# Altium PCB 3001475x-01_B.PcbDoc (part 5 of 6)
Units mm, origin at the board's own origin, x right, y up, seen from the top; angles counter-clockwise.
Board outline 335 x 91 mm, 12 copper layers (Top Layer, L2 GND, Layer 3, L4 GND, Layer 5, L6 PWR, L7 3V3, Layer 8, L9 GND, Layer 10, L11 GND, Bottom Layer), stack 1.59 mm thick; 339 components, 431 nets, 1732 pads, 1526 vias.
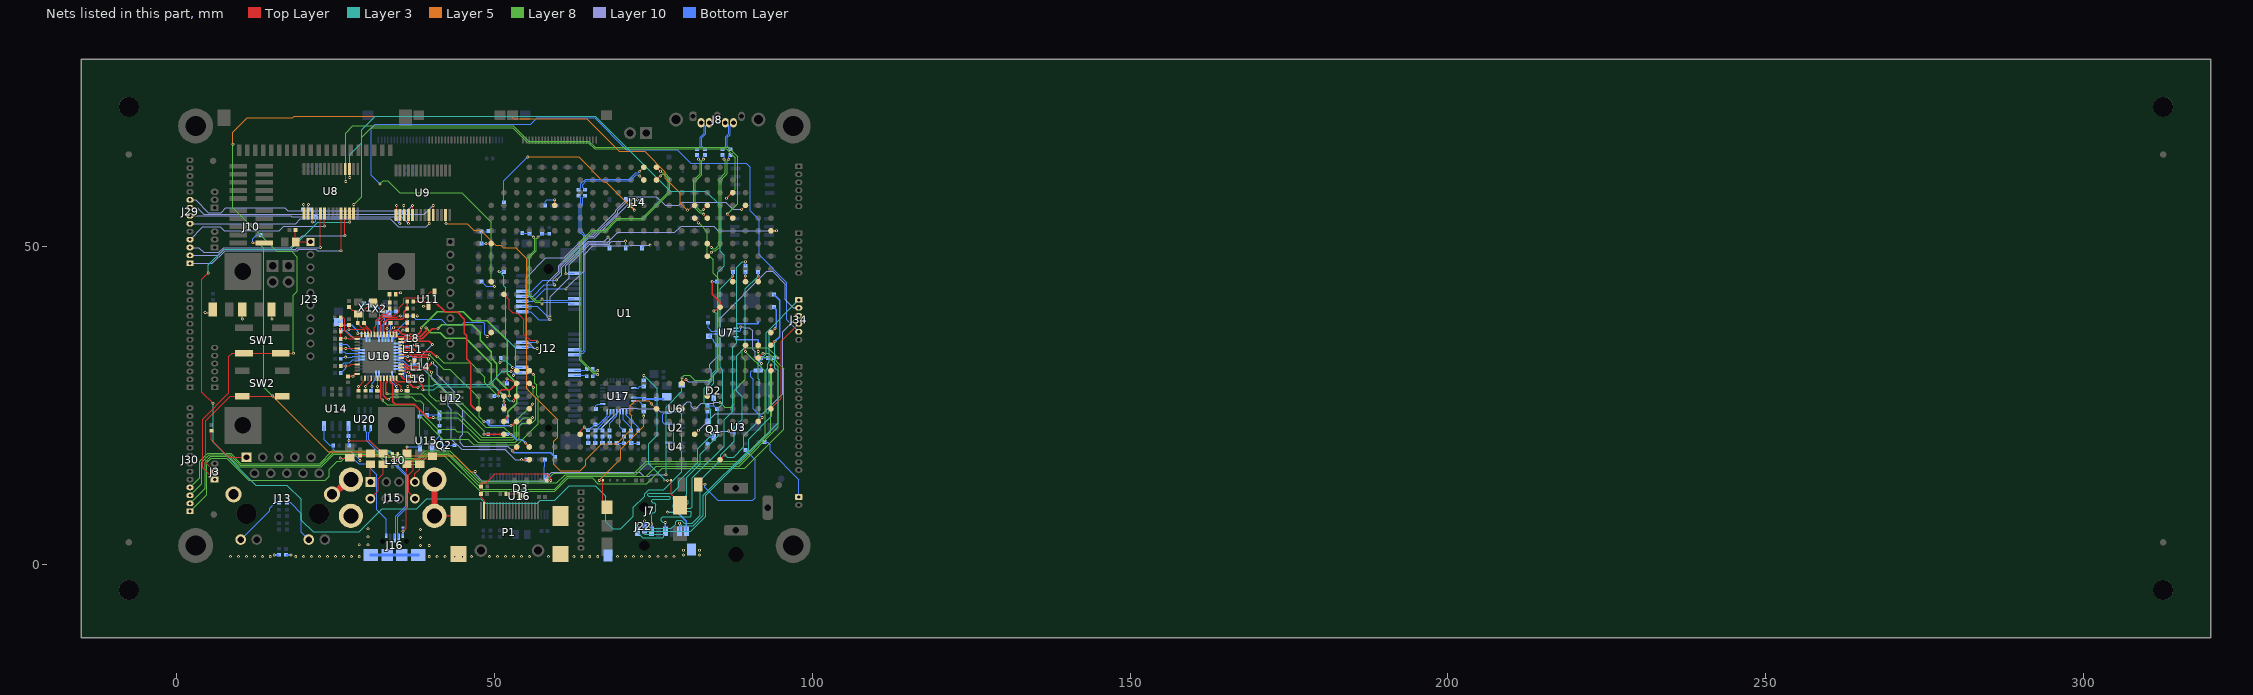
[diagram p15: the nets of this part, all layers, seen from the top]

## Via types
v1: diameter 0.45, hole 0.2, Top Layer to Bottom Layer, 1511 vias
v2: diameter 0.5, hole 0.2, Top Layer to Bottom Layer, 14 vias
v3: diameter 0.45/0.45/0.45/0.45/0.45/0.45/0.45/0.45/0.45/0.45/0.45/0.45 (per signal layer), hole 0.2, Top Layer to Bottom Layer, 1 vias

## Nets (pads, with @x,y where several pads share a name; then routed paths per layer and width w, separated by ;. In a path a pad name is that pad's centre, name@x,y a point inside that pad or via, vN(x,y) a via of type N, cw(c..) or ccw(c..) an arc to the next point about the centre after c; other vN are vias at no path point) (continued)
NetC22_1: C22.1 U8.1 | length 2
  Top Layer w0.125: U8.1@20,55.297 v1(20,56.625)
  Bottom Layer w0.125: C22.1@20,55.96 v1(20,56.625)
NetC22_2: C22.2 U8.2 | length 2
  Top Layer w0.125: U8.2@20.75,55.303 v1(20.75,56.625)
  Bottom Layer w0.125: C22.2@20.75,55.96 v1(20.75,56.625)
NetC23_1: C23.1 U9.1 | length 2.4
  Top Layer w0.125: U9.1@34.625,55.1 v1(34.625,56.5)
  Bottom Layer w0.125: C23.1@34.625,55.46 v1(34.625,56.5)
NetC23_2: C23.2 U9.2 | length 2.4
  Top Layer w0.125: v1(35.125,53.625) U9.2@35.125,54.95
  Bottom Layer w0.125: C23.2@34.625,54.54 34.625,54.125 v1(35.125,53.625)
NetC24_1: C24.1 U8.3 | length 2.6
  Top Layer w0.125: v1(21.375,53.875) U8.3@21.375,55.222
  Bottom Layer w0.125: v1(21.375,53.875) 21.75,53.875 21.875,54 C24.1@21.875,54.665
NetC25_1: C25.1 U9.3 | length 2.5
  Top Layer w0.125: U9.3@35.75,55.075 v1(35.75,56.5)
  Bottom Layer w0.125: C25.1@35.75,55.46 v1(35.75,56.5)
NetC28_2: C28.2 R39.2 U10.46 X1.1 | length 6.1
  Top Layer w0.125: C28.2@27.125,40.54 27.665,40 28.025,40 X1.1@28.6,39.425 ; R39.2@28.52,37.875 29.143,37.253 29.747,37.253 30.125,36.875 U10.46@30.125,36.2 ; R39.2@28.52,38 X1.1@28.52,39.425
NetC29_2: C29.2 J13.1 | length 8
  Top Layer w0.125: C29.2@5.5,21.04 5.5,19.625 8.235,16.89 J13.1@11,16.89
NetC30_2: C30.2 R39.1 U10.45 X1.3 | length 7.9
  Top Layer w0.125: X1.3@30.513,41.013 29.438,39.938 29.438,38.042 R39.1@29.48,38 29.48,37.874 30.625,36.729 U10.45@30.625,36.2 ; X1.3@30.9,41.325 31.09,41.325 C30.2@32.5,39.915
NetC42_2: C42.2 C43.2 C44.2 C45.2 L2.2 U10.1 U10.12 U10.47 | length 10.3
  Top Layer w0.125: C45.2@25.835,35.5 C42.2@25.835,36.625 L2.2@25.835,37.855 ; C45.2@25.96,35.625 v1(26.625,35.625) 27,35.625 27.125,35.5 U10.1@28.425,35.5 ; C44.2@27.125,37.665 v1(27.125,37.002) 29.498,37.002 29.625,36.875 U10.47@29.625,36.2
  Top Layer w0.25: C43.2@27.04,29.625 v1(27.75,29.625) 28.125,30 U10.12@28.425,30
NetC46_2: C46.2 C47.2 C48.2 C49.2 L3.1 U10.16 U10.34 U10.40 | length 8.2
  Top Layer w0.125: C46.2@29.75,27.335 v1(29.75,28) 29.75,28.125 30.625,29 U10.16@30.625,29.3 ; U10.40@33.125,36.2 v1(33.125,37.125) 33.125,37.46 C47.2@33.665,38 ; U10.34@35.325,34.5 v1(37.125,34.5) C48.2@37.79,34.5 ; L3.1@36.25,27.355 36.375,27.48 v1(36.375,28)
  Bottom Layer w0.125: C49.2@36.375,27.335 v1(36.375,28)
NetC50_2: C50.2 C51.2 C52.2 C53.2 C54.2 C55.2 C56.2 L4.1 U10.14 U10.18 U10.23 U10.26 U10.30 U10.39 | length 17.5
  Top Layer w0.125: C50.2@28.625,27.335 v1(28.625,28) 29.625,29 U10.14@29.625,29.3 ; C51.2@31.625,27.46 v1(31.625,28) U10.18@31.625,29.3 ; U10.39@33.625,36.2 33.625,36.75 v1(34.125,37.25) 34.25,37.375 36.29,37.375 ; U10.23@34.125,29.3 34.125,29 34.725,28.4 34.975,28.4 35.375,28 v1(35.375,27.375) 35.375,27.335 C52.2@34.625,27.335 ; U10.26@35.325,30.5 35.875,30.5 36.125,30.25 v1(36.5,30.25) C53.2@37.04,29.71 ; U10.30@35.325,32.5 35.875,32.5 36.375,32 v1(36.75,32) C54.2@37.165,32 ; C56.2@36.29,36.875 36.29,37.375 ; L4.1@36.29,39.25 C55.2@36.29,38 36.29,37.375
NetC60_2: C60.2 C61.2 L5.2 U10.44 | length 7.7
  Top Layer w0.125: U10.44@31.125,36.2 31.125,37.25 31.375,37.5 31.375,38.375 32.375,39.375 33.125,39.375 33.52,39.77 L5.2@33.52,42.5
NetC63_1: C63.1 R67.1 U13.32 X2.3 | length 7.6
  Bottom Layer w0.125: C63.1@29.535,41.05 X2.3@30.9,41.05 31.075,41.05 32,40.125 32,38.75 31.75,38.5 31.75,37.5 31.875,37.375 U13.32@31.875,35.55
NetC64_1: C64.1 R67.2 U13.33 X2.1 | length 5.7
  Bottom Layer w0.125: U13.33@32.375,35.55 32.375,37.645 R67.2@32.73,38 32.73,39.08 X2.1@33.1,39.45 33.44,39.79 C64.1@34.5,39.79
NetC66_2: C66.2 C67.2 L9.2 R72.1 U12.8 U15.S | length 13
  Top Layer w0.125: L9.2@36.25,17.475 v1(36.25,18.5)
  Bottom Layer w0.125: v1(36.25,18.5) U15.S@38.15,18.5 ; U15.S@38.3,18.55 38.663,18.913 38.663,19.712 38.25,20.125 C67.2@38.25,23.29 38.25,23.54 C66.2@39.375,23.54 ; C66.2@39.385,23.55 U12.8@41.345,23.55 ; R72.1@41.375,21.855 U12.8@41.375,23.52
NetC68_2: C68.2 C71.2 L7.2 U14.8 | length 11.6
  Top Layer w0.125: v1(28.875,16.375) C71.2@28.875,17.165 L7.2@30.19,17.165
  Bottom Layer w0.125: U14.8@23.22,21.8 23.22,19.655 24.125,18.75 C68.2@24.665,18.75 24.665,18.125 24.955,17.835 27.415,17.835 v1(28.875,16.375)
NetC69_2: C69.2 C70.2 L6.2 U14.5 | length 9.1
  Top Layer w0.125: v1(27.125,19.5) 30.375,19.5 32.4,17.475 L6.2@32.5,17.475
  Bottom Layer w0.125: C70.2@27.03,20.26 U14.5@27.03,21.8 ; C69.2@27.125,18.79 v1(27.125,19.5) C70.2@27.125,20.165
NetC72_2: C72.2 C73.2 C74.2 C75.2 C76.2 C77.2 L17.1 U13.5 U13.10 U13.15 U13.23 U13.29 U13.36 | length 21.4
  Bottom Layer w0.125: C77.2@25.835,32.625 v1(26.625,32.625) 27.625,32.625 27.75,32.75 U13.23@29.075,32.75 ; v1(28.5,36.375) 30.25,36.375 30.375,36.25 U13.29@30.375,35.55 ; C73.2@30.75,27.335 v1(30.75,28) 30.75,28.5 31.375,29.125 U13.15@31.375,29.95 ; U13.10@33.875,29.95 33.875,28.75 v1(34.625,28) C74.2@34.625,27.335 ; U13.36@33.875,35.55 34.175,35.55 35.5,36.875 v1(35.625,36.875) C76.2@36.29,36.875 ; U13.5@34.675,32.75 v1(36.375,32.75) 37.125,32.75 37.29,32.585 C75.2@37.29,32.5
  Bottom Layer w0.25: L17.1@25.5,38.15 25.985,37.665 C72.2@27.125,37.665 27.585,37.665 28.5,36.75 v1(28.5,36.375)
NetC78_2: C78.2 U13.14 | length 2.9
  Bottom Layer w0.125: C78.2@31.75,27.335 32.125,27.71 32.125,28.75 31.875,29 U13.14@31.875,29.95
NetC79_2: C79.2 U13.34 | length 2.8
  Bottom Layer w0.125: U13.34@32.875,35.55 32.875,36.25 33.665,37.04 C79.2@33.665,38
NetC84_2: C84.2 U16.37 | length 2.9
  Bottom Layer w0.138: U16.37@57.875,13.65 57.875,15.375 57.96,15.46 C84.2@57.96,16.5
NetC86_2: C86.2 P1.18 R85.2 R87.2 U16.38 | length 18.2
  Top Layer w0.125: R85.2@47.895,12.25 47.895,12.77 48,12.875 48.75,12.875 50.125,14.25 58.25,14.25 58.875,13.625 v1(58.875,13.25) R87.2@58.23,13.25 ; R85.2@47.915,12.25 C86.2@47.915,11.125 47.915,10.585 48.375,10.125 P1.18@48.375,8.5
  Bottom Layer w0.125: U16.38@58.375,13.65 58.375,13.25 v1(58.875,13.25)
NetC87_1: C87.1 U17.11 | length 3.5
  Bottom Layer w0.125: U17.11@70.25,24.05 70.25,22.75 71.5,21.5 C87.1@71.5,21.085
NetC87_2: C87.2 L18.1 R92.2 | length 2.2
  Bottom Layer w0.125: C87.2@71.5,20.165 L18.1@71.5,19.105 R92.2@72.625,19.105
NetC88_1: C88.1 U17.12 | length 3.2
  Bottom Layer w0.125: U17.12@69.75,24.05 69.75,21.71 C88.1@70.375,21.085
NetC88_2: C88.2 L19.1 R91.2 | length 2.2
  Bottom Layer w0.125: L19.1@69.25,19.105 R91.2@70.375,19.105 C88.2@70.375,20.165
NetC89_2: C89.2 U17.18 | length 1.7
  Bottom Layer w0.125: C89.2@65.96,24.5 65.96,24.96 66.25,25.25 U17.18@67.05,25.25
NetC90_2: C90.2 U17.10 | length 3.7
  Bottom Layer w0.125: U17.10@70.75,24.05 70.75,23.5 72.625,21.625 C90.2@72.625,21.085
NetC91_1: C91.1 L20.2 | length 1.1
  Bottom Layer w0.125: L20.2@68.125,19.105 C91.1@68.125,20.165
NetC91_2: C91.2 U17.13 | length 3.4
  Bottom Layer w0.125: C91.2@68.125,21.085 68.125,22.25 69.25,23.375 U17.13@69.25,24.05
NetC92_1: C92.1 L21.2 | length 1.1
  Bottom Layer w0.125: L21.2@67,19.105 C92.1@67,20.165
NetC92_2: C92.2 U17.14 | length 3.7
  Bottom Layer w0.125: C92.2@67,21.085 67,21.625 68.75,23.375 U17.14@68.75,24.05
NetC93_1: C93.1 L22.2 | length 1.1
  Bottom Layer w0.125: L22.2@65.875,19.105 C93.1@65.875,20.165
NetC93_2: C93.2 U17.15 | length 3.9
  Bottom Layer w0.125: C93.2@65.875,21.085 68.25,23.46 U17.15@68.25,24.05
NetC94_2: C94.2 R94.2 U17.16 | length 4.6
  Bottom Layer w0.125: R94.2@64.75,21.105 65.25,21.605 65.355,21.605 65.79,22.04 C94.2@65.875,22.04 66.415,22.04 67.75,23.375 U17.16@67.75,24.05
NetC97_2: C97.2 C98.2 L26.2 U17.5 | length 4.8
  Bottom Layer w0.25: U17.5@71.95,26.25 73.25,26.25 73.46,26.04 C98.2@75.5,26.04 L26.2@76.64,26.04
NetC101_2: C101.2 J23.1 L28.1 | length 4.2
  Top Layer w0.15: L28.1@18.71,50.765 C101.2@18.71,52.625 ; L28.1@18.725,50.75 J23.1@21.064,50.75
NetD1_A: D1.A R12.1 | length 18.6
  Top Layer w0.125: D1.A@82.05,12.625 v1(83.125,12.625)
  Bottom Layer w0.125: v1(83.125,12.625) 83.125,12.125 85.125,10.125 90.625,10.125 91,10.5 91,16.52 R12.1@89.5,18.02
NetD2_K: D2.K R11.1 R13.1 | length 2.9
  Bottom Layer w0.125: R13.1@83.52,25 84.5,25 ; D2.K@84.5,26.225 84.5,25 ; R11.1@85.02,24.5 84.52,25 84.5,25
NetD3_K: D3.K R86.1 | length 2.2
  Top Layer w0.125: R86.1@51.855,11.125 D3.K@54.1,11.125
NetD4_A: D4.A R119.1 | length 2.5
  Top Layer w0.125: v1(15,38.625) D4.A@15,40.075
  Bottom Layer w0.125: v1(15,38.625) R119.1@15,39.645
NetD5_A: D5.A R120.1 | length 2.5
  Top Layer w0.125: v1(10.375,38.625) D5.A@10.375,40.075
  Bottom Layer w0.125: v1(10.375,38.625) R120.1@10.375,39.645
NetD6_A: D6.A R121.1 | length 2
  Top Layer w0.125: v1(4.5,39.645) D6.A@5.22,39.645
  Bottom Layer w0.125: v1(4.5,39.645) R121.1@5.75,39.645
NetD7_2: D7.2 J22.3 L25.2 | length 17.9
  Top Layer w0.125: v1(66.5,13.25) D7.2@67.075,13.25 J22.3@67.075,9.625
  Layer 5 w0.125: v1(66.5,13.25) 69.875,16.625 69.875,18.125 73.5,21.75 v1(73.5,23.35) v1@73.5,23.375
  Bottom Layer w0.125: v1(73.5,23.35) L25.2@73.5,24.02
NetD8_2: D8.2 J22.2 L24.2 | length 24.9
  Top Layer w0.125: v1(77.25,13.25) D8.2@77.8,13.25 77.8,11.075 J22.2@79.2,9.675
  Layer 3 w0.125: v1(73.5,29.75) 75.625,27.625 75.625,20.375 74.25,19 74.25,15.875 76.875,13.25 v1(77.25,13.25)
  Bottom Layer w0.125: L24.2@73.5,28.98 v1(73.5,29.75)
NetD10_2: D10.2 J16.1 L9.1 | length 12.1
  Top Layer w0.125: v1(35.625,5.25) 36.125,5.75 36.125,14.625 36.25,14.75 L9.1@36.25,15.775
  Bottom Layer w0.125: J16.1@35.625,4.525 v1(35.625,5.25) D10.2@35.625,5.825
NetJ2_1: J2.1 R8.1 | length 11.2
  Bottom Layer w0.125: R8.1@92.48,19.25 93,19.25 93.375,18.875 93.375,17.875 97.875,13.375 J2.1@97.875,10.625
NetJ7_5: J7.5 R35.2 | length 54
  Layer 3 w0.104: v1(76.875,6.625) 76.5,6.625 76.25,6.875 76.25,7.25 76.5,7.5 80.833,7.5 81,7.667 81,8.25 80.875,8.375 79.875,8.375 79.75,8.5 79.75,8.75 79.875,8.875 80.875,8.875 81.125,9.125 81.125,13.625 86.125,18.625 86.125,22.75 87.5,24.125 87.5,34.25 88.125,34.875 88.125,46.75 89,47.625 v1(89.5,47.625)
  Bottom Layer w0.2: J7.5@76.875,5.275 v1(76.875,6.625) ; R35.2@89.5,46.98 v1(89.5,47.625)
NetJ13_D1: J13.D1 R45.1 | length 8.7
  Bottom Layer w0.125: J13.D1@10.086,3.936 14.625,8.475 14.625,8.875 15.52,9.77 R45.1@16.125,9.77
NetJ13_D3: J13.D3 R38.1 | length 7.5
  Bottom Layer w0.125: R38.1@17.375,9.77 17.855,9.77 19.625,8 19.625,5.115 J13.D3@20.804,3.936
NetJ15_A1: J15.A1 L7.1 | length 2.8
  Top Layer w0.125: J15.A1@30.5,13 L7.1@30.5,15.775
NetJ15_A4: J15.A4 L13.2 | length 3.1
  Top Layer w0.125: J15.A4@37.5,13 37.5,14.25 38.25,15 L13.2@38.25,15.775
NetJ15_B1: J15.B1 L6.1 | length 6.2
  Top Layer w0.125: J15.B1@30.5,10.38 31.75,11.63 31.75,13.5 32.5,14.25 L6.1@32.5,15.775
NetJ15_B4: J15.B4 L12.2 | length 10.1
  Top Layer w0.125: J15.B4@37.5,10.38 36.5,11.38 36.5,14.125 37.25,14.875 37.25,16.5 37.375,16.625 39.85,16.625 L12.2@40.25,17.025
NetJ16_5: J16.5 L15.2 | length 18.6
  Top Layer w0.125: v1(25.75,16.75) L15.2@27.225,16.75
  Bottom Layer w0.125: v1(25.75,16.75) 27.75,16.75 28.625,15.875 29.75,15.875 31.5,14.125 31.5,8.625 33,7.125 J16.5@33,4.525 J16.5@33,4.5
NetL1_1: L1.1 U7.5 | length 4.5
  Bottom Layer w0.25: U7.5@88,37.175 88.125,37.3 88.125,37.875 91.5,37.875 L1.1@91.5,38.1 L1.1@91.5,38.225
NetL1_2: L1.2 U7.8 | length 4.4
  Bottom Layer w0.25: U7.8@88,35.825 88,35.375 91.5,35.375 L1.2@91.5,34.9
NetL8_1: L8.1 U13.1 | length 2.2
  Bottom Layer w0.125: U13.1@34.675,34.75 35,34.75 35.5,35.25 35.5,35.5 35.9,35.9 L8.1@36.275,35.9
NetL8_4: L8.4 U13.2 | length 2
  Bottom Layer w0.125: U13.2@34.675,34.25 35.125,34.25 35.975,35.1 L8.4@36.275,35.1
NetL11_1: L11.1 U13.3 | length 1.8
  Bottom Layer w0.125: U13.3@34.675,33.75 35.5,33.75 36.025,34.275 L11.1@36.275,34.275
NetL11_4: L11.4 U13.4 | length 1.7
  Bottom Layer w0.125: U13.4@34.675,33.25 35.75,33.25 36,33.5 L11.4@36.275,33.5
NetL14_1: L14.1 U13.6 | length 3.3
  Bottom Layer w0.125: U13.6@34.675,32.25 35.5,32.25 36.375,31.375 37.375,31.375 L14.1@37.525,31.525
NetL14_4: L14.4 U13.7 | length 3.1
  Bottom Layer w0.125: U13.7@34.675,31.75 35.5,31.75 36.525,30.725 L14.4@37.4,30.725
NetL16_1: L16.1 U13.8 | length 3.2
  Bottom Layer w0.125: U13.8@34.675,31.25 35.375,31.25 36,30.625 36,29.875 36.225,29.65 L16.1@36.775,29.65
NetL16_4: L16.4 U13.9 | length 3.3
  Bottom Layer w0.125: U13.9@34.675,30.75 35.375,30.75 35.625,30.5 35.625,29.75 36.525,28.85 L16.4@36.775,28.85
NetL23_2: L23.2 R94.1 | length 1
  Bottom Layer w0.125: L23.2@64.75,19.105 R94.1@64.75,20.145
NetL24_1: L24.1 U17.2 | length 1.7
  Bottom Layer w0.125: U17.2@71.95,27.75 72.625,27.75 72.895,28.02 L24.1@73.5,28.02
NetL25_1: L25.1 U17.6 | length 1.9
  Bottom Layer w0.125: U17.6@71.95,25.75 72.73,25.75 L25.1@73.5,24.98
NetQ1_1: Q1.1 R13.2 | length 1.5
  Bottom Layer w0.125: Q1.1@83.5,22.5 R13.2@83.5,24.02
NetQ1_3: Q1.3 R14.2 U3.3 | length 6.2
  Layer 10 w0.125: v1(84.5,21) v1(86.875,21)
  Bottom Layer w0.125: R14.2@83.5,18.98 83.5,19.75 83.8,20.05 Q1.3@84.5,20.05 v1(84.5,21) ; v1(86.875,21) 87.16,20.715 U3.3@87.725,20.715
NetQ2_D: Q2.D R72.2 U15.G | length 4.7
  Bottom Layer w0.125: U15.G@40.2,18.35 40.2,19.075 41.375,20.25 R72.2@41.375,20.895 ; U15.G@40.49,18.06 Q2.D@42.125,18.06
NetQ2_G: Q2.G R75.2 | length 2.7
  Bottom Layer w0.125: Q2.G@41.625,19.44 41.625,19 41.855,18.77 R75.2@43.75,18.77
NetR1_1: R1.1 R2.1 R3.1 U1.G2 | length 4.3
  Top Layer w0.125: v1(48.675,50.5) U1.G2@49.5,50.5
  Bottom Layer w0.125: v1(48.675,50.5) R1.1@47.98,50.5 R3.1@47.98,52.375 R2.1@48.895,52.375
NetR4_1: R4.1 U1.D13 | length 29.8
  Top Layer w0.125: U1.D13@71.5,56.5 v1(72,55.75)
  Layer 5 w0.125: v1(55.25,64.125) 63.25,64.125 67.125,60.25 67.5,60.25 v1(72,55.75)
  Bottom Layer w0.125: R4.1@51.5,56.98 51.5,60.375 v1(55.25,64.125)
NetR5_2: R5.2 U1.D7 | length 3.1
  Top Layer w0.125: U1.D7@59.5,56.5 v1(59.5,57.375)
  Bottom Layer w0.125: R5.2@57.98,56.5 57.98,57.105 58.25,57.375 v1(59.5,57.375)
NetR22_1: R22.1 R123.2 R124.2 U7.6 | length 12.2
  Layer 10 w0.125: v1(88.75,37.375) 89.125,37.375 89.25,37.25 90.125,37.25 90.625,36.75 90.625,33.875 91,33.5 91,32.625 v1(92,31.625)
  Bottom Layer w0.125: U7.6@88,36.725 88.6,36.725 88.75,36.875 v1(88.75,37.375) ; R123.2@91.98,30.5 R22.1@91.98,32.5 R124.2@93.02,32.5
NetR23_1: R23.1 R27.2 U7.2 | length 3.4
  Bottom Layer w0.125: U7.2@85,36.275 84.1,36.275 R27.2@83.75,35.925 83.825,35.925 84.5,35.25 84.5,35.02 R23.1@85.02,34.5
NetR26_2: R26.2 U7.3 | length 2.4
  Bottom Layer w0.125: R26.2@83.625,38.02 83.625,37.25 84.15,36.725 U7.3@85,36.725
NetR48_2: R48.2 R50.2 U10.41 | length 8
  Top Layer w0.2: U10.41@32.625,36.2 32.625,38 33.2,38.575 35.45,38.575 35.725,38.85 35.725,39.705 R50.2@36.27,40.25 R48.2@36.27,41.375
NetR49_2: R49.2 U10.48 | length 5.6
  Top Layer w0.125: R49.2@25.855,38.875 26.25,38.875 26.5,38.625 26.5,36.75 27.375,35.875 U10.48@29.125,35.875
NetR68_1: R68.1 U13.28 | length 4.6
  Bottom Layer w0.125: R68.1@25.855,36.875 26.625,36.875 27.95,35.55 U13.28@29.875,35.55
NetR70_2: R70.2 U13.35 | length 4.3
  Bottom Layer w0.125: U13.35@33.375,35.55 33.375,36.25 33.75,36.625 34.5,36.625 35.875,38 R70.2@36.27,38
NetR71_2: R71.2 U13.22 | length 3.6
  Bottom Layer w0.125: R71.2@25.875,31.25 26.375,31.75 27.25,31.75 27.75,32.25 U13.22@29.075,32.25
NetR73_2: R73.2 U13.24 | length 3.3
  Bottom Layer w0.125: R73.2@25.855,33.5 26.375,33.5 26.625,33.25 U13.24@29.075,33.25
NetR74_2: R74.2 U13.25 | length 3.6
  Bottom Layer w0.125: R74.2@25.855,34.625 26.75,34.625 27.625,33.75 U13.25@29.075,33.75
NetU2_6: U2.6 U4.6 U6.4 | length 7.6
  Bottom Layer w0.125: U6.4@77.375,23.875 76.75,23.875 76.5,23.625 76.5,22.4 76.75,22.15 U2.6@77.4,22.15 78,22.15 78.25,21.9 78.25,19.375 78.025,19.15 U4.6@77.4,19.15
NetU10_43: U10.43 U11.G | length 13.7
  Top Layer w0.125: U10.43@31.625,36.2 31.625,38.25 32.5,39.125 34.25,39.125 35,39.875 35,40.375 35.75,41.125 35.75,41.875 35.875,42 39.125,42 40.025,42.9 U11.G@40.575,42.9
ON/OFF: J3.1 SW1.3 SW1.4 U1.D18 | length 154.2
  Top Layer w0.125: J3.1@6,13.375 4.125,15.25 4.125,22.875 8.25,27 8.25,32.75 8.75,33.25 SW1.3@10.6,33.25 SW1.4@16.4,33.25 v1(18.375,33.25) ; v1(80.375,55.75) U1.D18@81.5,56.5
  Layer 8 w0.125: v1(8.875,66.125) 8.875,56.125 15.75,49.25 18.125,49.25 19,48.375 19,43 18.375,42.375 v1(18.375,33.25)
  Layer 5 w0.125: v1(8.875,66.125) 8.875,68 11.125,70.25 18.25,70.25 18.5,70.5 52.625,70.5 53,70.125 64.5,70.125 69.625,65 73.625,65 76.875,61.75 76.875,60.75 79.25,58.375 79.25,56.875 v1(80.375,55.75)
OTGD_N: J16.2 L10.2 U20.4 | length 22.8
  Top Layer w0.155: v1(34.75,16.375) 34.75,16.673 34.775,16.698 L10.2@34.775,17.225
  Bottom Layer w0.155: U20.4@30.575,21.475 30.575,21.075 30.242,20.742 30.242,19.607 31.965,17.885 33.643,17.885 34.518,17.011 34.518,16.607 v1(34.75,16.375) 34.518,16.143 34.518,15.886 36.4,14.003 36.4,9.133 34.767,7.5 34.767,4.932 34.95,4.75 J16.2@34.95,4.15
OTGD_P: J16.3 L10.3 U20.5 | length 22.8
  Top Layer w0.155: L10.3@33.975,17.225 33.975,16.698 34,16.673 v1(34,16.375)
  Bottom Layer w0.155: U20.5@29.625,21.475 29.625,21.1 29.957,20.768 29.957,19.489 31.847,17.6 33.525,17.6 34.232,16.893 34.232,16.607 v1(34,16.375) 34.232,16.143 34.232,15.767 36.115,13.885 36.115,9.251 34.482,7.618 34.482,4.932 34.3,4.75 J16.3@34.3,4.15
PCIE_DIS_N: J12.20 U1.L3 | length 13
  Top Layer w0.125: U1.L3@51.5,42.5 52.375,41.625 52.375,40.125 52.875,39.625 53.625,39.625 54.625,38.625 54.625,36.25 55.625,35.25 56.5,35.25 v1(56.75,35)
  Bottom Layer w0.125: J12.20@54.4,35 v1(56.75,35)
PCIE_I2C_SCL: J12.30 R95.2 | length 4.8
  Layer 3 w0.125: v1(50.875,31.8) 51.125,32.05 51.825,32.05 v1(52.875,31)
  Bottom Layer w0.125: v1(50.875,31.8) 50.875,32.355 R95.2@51.02,32.5 ; v1(52.875,31) J12.30@54.4,31
PCIE_I2C_SDA: J12.32 R96.2 | length 20.2
  Layer 3 w0.125: v1(50.75,46.125) 51.5,45.375 51.5,43.828 51.75,43.578 51.75,35.625 53.375,34 53.375,30.125 v1(53,29.75)
  Bottom Layer w0.125: v1(50.75,46.125) 51.395,46.125 R96.2@51.5,46.02 ; v1(53,29.75) 53,30.125 53.075,30.2 J12.32@54.4,30.2
PCIE_RESET_N: J12.22 U1.D22 | length 56
  Top Layer w0.125: v1(88.875,55.875) U1.D22@89.5,56.5
  Layer 10 w0.125: v1(56.75,34) 56.25,34 55,35.25 55,45.146 58.104,48.25 61,48.25 64.625,51.875 65.5,51.875 69.125,55.5 69.125,55.75 71.25,57.875 75.5,57.875 76.875,56.5 79,56.5 79.5,57 86.375,57 87.5,55.875 v1(88.875,55.875)
  Bottom Layer w0.125: J12.22@54.4,34.2 55.925,34.2 56.125,34 v1(56.75,34)
PCIE_RX_N: R44.1 U1.A14 | length 12
  Top Layer w0.175: v1(72.875,61.875) U1.A14@73.5,62.5
  Bottom Layer w0.175: R44.1@63.25,58.98 63.6,59.33 63.6,59.9 64.35,60.65 71.225,60.65 72.225,61.65 72.65,61.65 v1(72.875,61.875)
PCIE_RX_P: R47.1 U1.B14 | length 11.5
  Top Layer w0.175: v1(72.875,61.125) U1.B14@73.5,60.5
  Bottom Layer w0.175: R47.1@64.25,58.98 63.9,59.33 63.9,59.776 64.474,60.35 71.349,60.35 72.349,61.35 72.65,61.35 v1(72.875,61.125)
PCIE_TX_N: R51.1 U1.A15 | length 45
  Top Layer w0.175: U1.A15@75.5,62.5 v1(76.125,61.875)
  Layer 8 w0.119: v1(66.25,30.5) 66.059,30.309 65.625,30.309 63.7,32.234 63.7,50.625 65.45,52.375 67.52,52.375 69.348,54.202 73.352,54.202 77.619,58.469 77.619,60.779 76.776,61.622 76.378,61.622 v1(76.125,61.875)
  Bottom Layer w0.175: R51.1@65.48,30.75 65.73,30.5 v1(66.25,30.5)
PCIE_TX_P: R52.1 U1.B15 | length 45
  Top Layer w0.175: U1.B15@75.5,60.5 v1(76.125,61.125)
  Layer 8 w0.119: v1(66.25,29.875) 66.059,30.065 65.524,30.065 63.456,32.133 63.456,50.726 65.349,52.619 67.419,52.619 69.175,54.375 69.246,54.446 73.251,54.446 77.375,58.57 77.375,60.678 76.675,61.378 76.378,61.378 v1(76.125,61.125)
  Bottom Layer w0.175: R52.1@65.48,29.625 65.73,29.875 v1(66.25,29.875)
PCIE_UIM_CLK: J12.12 J14.3 | length 26.7
  Layer 10 w0.125: v1(61.25,43.375) 64.125,46.25 64.125,48.75 65.5,50.125 71.25,50.125 71.375,50.25 v1(74.5,50.25)
  Bottom Layer w0.125: J12.12@54.4,41.4 56.025,41.4 58,43.375 v1(61.25,43.375) ; J14.3@73.2,49.795 73.655,50.25 v1(74.5,50.25)
PCIE_UIM_DATA: J12.10 J14.7 | length 26.5
  Layer 10 w0.125: v1(59.5,44) 59.25,44.25 59.25,44.875 60.375,46 60.375,46.896 64.854,51.375 65.75,51.375 71,56.625 71.75,56.625 v1(72.5,57.375)
  Bottom Layer w0.125: J12.10@54.4,42.2 56.075,42.2 57.875,44 v1(59.5,44) ; v1(72.5,57.375) J14.7@73.2,57.415
PCIE_UIM_PWR: J12.8 J14.1 | length 19.5
  Layer 10 w0.125: v1(59.75,44.75) 60.625,45.625 60.625,46.75 64.75,50.875 67.25,50.875 v1(67.875,51.5)
  Bottom Layer w0.125: J12.8@54.4,43 55.875,43 57.625,44.75 v1(59.75,44.75) ; v1(67.875,51.5) 68.12,51.255 J14.1@68.12,49.795
PCIE_UIM_RST: J12.14 J14.2 | length 25.7
  Layer 10 w0.125: v1(58.75,39.125) 58.75,42.125 61.75,45.125 61.75,47.125 65,50.375 68,50.375 68.5,50.875 v1(70.625,50.875)
  Bottom Layer w0.125: J12.14@54.4,40.6 56.775,40.6 58.25,39.125 v1(58.75,39.125) ; J14.2@70.625,49.83 v1(70.625,50.875)
PCIE_UIM_VPP: J12.16 J14.6 | length 30.9
  Layer 10 w0.125: v1(58.75,38.5) 58.337,38.913 58.337,44.337 60.125,46.125 60.125,47 64.75,51.625 65.625,51.625 69.375,55.375 69.375,55.646 71.104,57.375 v1(71.5,57.375)
  Bottom Layer w0.125: J12.16@54.4,39.8 55.7,39.8 57,38.5 v1(58.75,38.5) ; J14.6@70.7,57.375 v1(71.5,57.375)
PCIE_WAKE_N: J12.1 U1.F24 | length 39.5
  Top Layer w0.125: U1.F24@93.5,52.5 v1(94.375,52.5)
  Layer 10 w0.125: v1(61.25,45.75) 61.25,47 64.875,50.625 67.75,50.625 69.375,52.25 78.375,52.25 79.375,53.25 84.5,53.25 85.25,52.5 v1(94.375,52.5)
  Bottom Layer w0.125: v1(61.25,45.75) 61.3,45.8 J12.1@62.6,45.8
PCIECLK_N: C31.2 J12.11 R43.2 | length 19.2
  Layer 8 w0.119: v1(56.875,51.5) 56.622,51.247 56.622,49.377 55.575,48.33 55.575,42.475 56.553,41.497 57.247,41.497 v1(57.5,41.75)
  Bottom Layer w0.175: v1(56.875,51.5) C31.2@57.5,52.04 R43.2@58.625,52.02 ; v1(57.5,41.75) 57.7,41.55 61.6,41.55 61.85,41.8 J12.11@62.6,41.8
PCIECLK_P: C32.2 J12.13 R42.2 | length 19.6
  Layer 8 w0.119: v1(56.125,51.5) 56.378,51.247 56.378,49.478 55.331,48.431 55.331,42.374 56.452,41.253 57.247,41.253 v1(57.5,41)
  Bottom Layer w0.175: R42.2@54.355,52.125 C32.2@55.415,52.125 ; C32.2@55.5,52.04 v1(56.125,51.5) ; v1(57.5,41) 57.75,41.25 61.575,41.25 61.825,41 J12.13@62.6,41
PCIERX_N: J12.23 R44.2 | length 26.4
  Bottom Layer w0.175: J12.23@62.6,33.8 63.375,33.8 63.625,33.55 63.826,33.55 64.025,33.749 64.025,51.7 63.375,52.35 63.375,56.55 63.6,56.775 63.6,57.67 R44.2@63.25,58.02
PCIERX_P: J12.25 R47.2 | length 26.9
  Bottom Layer w0.175: J12.25@62.6,33 63.375,33 63.625,33.25 63.95,33.25 64.325,33.625 64.325,51.824 63.675,52.474 63.675,56.426 63.9,56.651 63.9,57.67 R47.2@64.25,58.02
PCIETX_N: J12.31 R51.2 | length 2
  Bottom Layer w0.175: J12.31@62.6,30.6 64.37,30.6 R51.2@64.52,30.75
PCIETX_P: J12.33 R52.2 | length 2
  Bottom Layer w0.175: J12.33@62.6,29.8 64.345,29.8 R52.2@64.52,29.625
POR_N: J3.2 J10.10 R7.1 R15.1 SW2.3 SW2.4 U1.E18 | length 170.3
  Top Layer w0.125: J3.2@6,14.625 4.625,16 4.625,22.65 8.475,26.5 SW2.3@10.35,26.5 v1(15.125,26.5) SW2.4@16.65,26.5 ; v1(12,50.625) J10.10@13.742,50.625 ; U1.E18@81.5,54.5 v1(82.125,53.75)
  Layer 8 w0.125: v1(12,50.625) 12.875,50.625 13.75,49.75 13.75,27.875 v1(15.125,26.5) ; v1(79.5,29.375) 79.875,29.75 80.75,29.75 81.5,29 83.75,29 85.25,30.5 85.25,34.021 85.25,45 84.462,45.788 84.462,47.913 83.5,48.875 83.5,52.375 v1(82.125,53.75)
  Layer 5 w0.125: v1(15.125,26.5) 23.875,17.75 29.75,17.75 30.375,17.125 43.75,17.125 46.25,14.625 v1(47,14.625)
  Layer 10 w0.125: v1(47,14.625) 47,14.25 48.125,13.125 57.625,13.125 59,14.5 72.875,14.5 73.5,13.875 74.375,13.875 74.625,14.125 v1(77,14.125)
  Layer 3 w0.125: v1(77,14.125) 77,24.75 79.5,27.25 v1(79.5,29.375)
  Bottom Layer w0.125: v1(12,50.625) 12,51.25 12.625,51.875 R7.1@13.27,51.875 ; R15.1@79.5,28.3 v1(79.5,29.375)
PWR_EN: R124.1 U1.AB9 | length 45.5
  Top Layer w0.125: U1.AB9@63.5,20.5 63.5,21 v1(64.125,21.625)
  Layer 8 w0.125: v1(85.5,25.5) 86.25,24.75 87.25,24.75 87.75,25.25 87.75,27.375 89.5,29.125 89.5,32.125 89,32.625 89,33.75 89.375,34.125 93,34.125 v1(94.625,32.5)
  Layer 10 w0.125: v1(64.125,21.625) 64.375,21.375 66.75,21.375 70,24.625 72.375,24.625 72.5,24.5 75.625,24.5 76.125,24 78.75,24 80.375,25.625 80.75,25.625 81,25.375 81,24.875 81.25,24.625 81.771,24.625 82.521,25.375 84.5,25.375 84.625,25.5 v1(85.5,25.5)
  Bottom Layer w0.125: R124.1@93.98,32.5 v1(94.625,32.5)
PWR_OK: R123.1 U1.AA23 | length 9.6
  Top Layer w0.125: U1.AA23@91.5,22.5 v1(92.125,23.125)
  Bottom Layer w0.125: R123.1@91.02,30.5 90.5,30.5 90.337,30.337 90.337,29.538 90.75,29.125 90.75,24.5 v1(92.125,23.125)
RGMII_1V2: C57.2 C58.2 C59.2 L4.2 L5.1 U10.4 U10.9 U11.D | length 8.8
  Top Layer w0.125: C58.2@25.835,31.25 v1(26.625,31.25) 27.25,31.25 27.5,31.5 U10.9@28.425,31.5 ; C59.2@25.835,34 v1(26.625,34) U10.4@28.425,34 ; L5.1@34.605,42.75 v1(35.25,42.75) v1@35.25,42.875 ; L4.2@37.355,39.125 v1(37.875,39.125) ; v1(38.875,40.625) U11.D@39.6,40.625
  Bottom Layer w0.125: C57.2@25.835,30.125 26.625,30.915 v1(26.625,31.25)
RGMII_INT_N: R40.1 U1.AA3 U10.38 | length 37.1
  Top Layer w0.2: U10.38@34.125,36.2 34.125,36.625 34.375,36.875 34.875,36.875 35.5,36.25 38,36.25 38.5,36.75 v1(38.5,37.25) ; U1.AA3@51.5,22.5 v1(52.125,23.375)
  Layer 8 w0.2: v1(38.5,37.25) 41,39.75 45.125,39.75 46.5,38.375 48.875,38.375 52,35.25 52,30 53.5,28.5 53.5,25.375 52.125,24 v1(52.125,23.375)
  Bottom Layer w0.2: R40.1@52.125,22.645 v1(52.125,23.375)
RGMII_MDC: U1.W3 U10.36 | length 26.4
  Top Layer w0.2: U10.36@35.325,35.5 38.625,35.5 40.25,37.125 40.875,37.125 ; U1.W3@51.5,26.5 v1(52.375,26.5)
  Layer 8 w0.2: v1(41.125,37.125) 41.75,37.75 46.5,37.75 47.75,36.5 47.75,35.25 49.5,33.5 49.5,32.5 50.375,31.625 50.375,29.25 52.375,27.25 v1(52.375,26.5)
RGMII_MDIO: R41.1 U1.Y3 U10.37 | length 27
  Top Layer w0.2: U10.37@34.625,36.2 34.625,35.875 38.375,35.875 39.25,36.75 v1(39.25,37.25) ; U1.Y3@51.5,24.5 v1(51.5,25.625)
  Layer 8 w0.2: v1(39.25,37.25) 40,36.5 41.5,36.5 42.375,35.625 45.5,35.625 49.5,31.625 49.5,28.5 51.5,26.5 v1(51.5,25.625)
  Bottom Layer w0.2: R41.1@51.5,24.98 v1(51.5,25.625)
RGMII_RD0: R60.1 U1.AA4 U10.32 | length 25.2
  Top Layer w0.2: U10.32@35.325,33.5 35.75,33.5 35.875,33.625 36.875,33.625 37.5,33 v1(39.75,33) ; v1(52.625,21.875) U1.AA4@53.5,22.5
  Layer 8 w0.104: v1(39.75,33) 42,30.75 43.011,30.75 47.625,26.136 47.625,23.25 v1(48.375,22.5)
  Bottom Layer w0.2: v1(48.375,22.5) R60.1@49.02,22.5 49.02,22.105 49.25,21.875 v1(52.625,21.875)
RGMII_RD1: R61.1 U1.AB3 U10.31 | length 25.7
  Top Layer w0.2: U10.31@35.325,33 35.875,33 36.125,33.25 36.636,33.25 37.261,32.625 39.375,32.625 v1(39.625,32.375) ; v1(48.375,20.5) U1.AB3@51.5,20.5
  Layer 8 w0.104: v1(39.625,32.375) 39.625,30 39.75,29.875 39.75,26.75 40.75,25.75 43.625,25.75 48.375,21 v1(48.375,20.5)
  Bottom Layer w0.2: v1(48.375,20.5) R61.1@49.02,20.5
RGMII_RD2: R62.1 U1.AC4 U10.28 | length 36.7
  Top Layer w0.2: U10.28@35.325,31.5 36,31.5 36.375,31.125 39.625,31.125 v1(40.25,31.75) ; v1(52.875,17.875) U1.AC4@53.5,18.5
  Layer 10 w0.104: v1(40.25,31.75) 41,31 41,29.875 43.7,27.175 43.7,25.55 45,24.25 45,20.5 44.625,20.125 44.625,19.125 45.125,18.625 52.125,18.625 v1(52.875,17.875)
  Bottom Layer w0.2: v1(52.875,17.875) 53.125,17.625 58.855,17.625 R62.1@59.5,16.98
RGMII_RD3: R63.1 U1.AC5 U10.27 | length 26.6
  Top Layer w0.2: U10.27@35.325,31 36,31 36.25,30.75 39.625,30.75 v1(40.125,30.25) ; v1(54.875,19.125) U1.AC5@55.5,18.5
  Layer 8 w0.104: v1(40.125,30.25) 40.125,29.25 42.375,27 43.25,27 47.925,22.325 47.925,22.314 48.614,21.625 51.5,21.625 v1(52.625,20.5)
  Bottom Layer w0.2: R63.1@51.98,20.5 v1(52.625,20.5) 53.5,19.625 54.375,19.625 v1(54.875,19.125)
RGMII_REF_CLK: R48.1 U1.Y1 | length 24.6
  Top Layer w0.2: R48.1@37.23,41.375 40.625,41.375 42.25,39.75 44.125,39.75 45.25,38.625 45.25,36.375 45.625,36 45.625,32.375 46.25,31.75 46.25,25.125 46.875,24.5 U1.Y1@47.5,24.5
RGMII_RESET_N: U1.P2 U10.42 | length 22.7
  Top Layer w0.125: U10.42@32.125,36.2 32.125,38.25 32.75,38.875 34.625,38.875 34.875,39.125 v1(35.25,39.125) ; v1(48.875,35.875) U1.P2@49.5,36.5
  Bottom Layer w0.125: v1(35.25,39.125) 37.125,39.125 37.625,38.625 41.625,38.625 42.5,37.75 44.875,37.75 45.25,38.125 48.25,38.125 48.5,37.875 48.5,36.25 v1(48.875,35.875)
RGMII_RX_CTL: R58.1 R59.1 U1.V4 U10.33 | length 26
  Top Layer w0.2: U10.33@35.325,34 36,34 37.125,34 37.625,33.5 40,33.5 40.75,32.75 v1(41,32.75) ; v1(50.625,26.5) 50.625,27 51.125,27.5 52.5,27.5 U1.V4@53.5,28.5 v1(51.98,29.23)
  Layer 8 w0.104: v1(41,32.75) 42,31.75 46.25,31.75 48.5,29.5 48.5,28.625 v1(50.625,26.5)
  Bottom Layer w0.2: R59.1@49.98,26.5 v1(50.625,26.5) ; R58.1@51.98,28.5 v1(51.98,29.23)
RGMII_RXC: R57.1 U1.AD5 U10.35 | length 37.1
  Top Layer w0.2: U10.35@35.325,35 36,35 36.125,35.125 39.75,35.125 v1(40.25,34.625) ; v1(54.25,16.5) U1.AD5@55.5,16.5
  Layer 10 w0.104: v1(40.25,34.625) 39.95,34.325 39.95,34.314 39.686,34.05 39.675,34.05 38.55,32.925 38.55,31.075 42.75,26.875 42.75,24.875 43.25,24.375 43.25,19.75 44.875,18.125 51.625,18.125 53.25,16.5 v1(54.25,16.5)
  Bottom Layer w0.2: v1(54.25,16.5) R57.1@55.02,16.5
RGMII_TD0: U1.U5 U10.19 | length 41.8
  Top Layer w0.2: U10.19@32.125,29.3 32.125,26.125 v1(32.375,25.875) ; U1.U5@55.5,30.5 v1(56.125,29.875)
  Layer 8 w0.104: v1(32.375,25.875) 33.125,25.125 37.5,25.125 38.25,24.375 38.25,23.375 41.875,19.75 45.875,19.75 46.75,18.875 53.625,18.875 56.875,22.125 56.875,26.375 56.625,26.625 56.625,28.25 56.375,28.5 56.375,29.625 v1(56.125,29.875)
RGMII_TD1: U1.V5 U10.20 | length 39.8
  Top Layer w0.2: U10.20@32.625,29.3 32.625,28.75 32.5,28.625 32.5,26.625 33.125,26 v1(33.375,26) ; U1.V5@55.5,28.5 v1(56.125,27.875)
  Layer 8 w0.104: v1(33.375,26) 33.75,26.375 37,26.375 37.625,25.75 38.375,25.75 38.875,25.25 38.875,23.489 41.114,21.25 43.75,21.25 44.125,20.875 45.75,20.875 47.375,19.25 53.25,19.25 53.875,19.875 53.875,21.75 54.375,22.25 55.875,22.25 56.5,22.875 56.5,26.25 56.125,26.625 v1(56.125,27.875)
RGMII_TD2: U1.Y5 U10.21 | length 32.7
  Top Layer w0.2: v1(33.125,26.875) 32.875,27.125 32.875,28.5 33.125,28.75 U10.21@33.125,29.3 ; U1.Y5@55.5,24.5 v1(56,25.25)
  Layer 8 w0.104: v1(33.125,26.875) 38.5,26.875 41.5,23.875 44.125,23.875 48,20 52.875,20 53.125,20.25 53.125,22.375 v1(56,25.25)
RGMII_TD3: U1.AA5 U10.22 | length 31.7
  Top Layer w0.2: U10.22@33.625,29.3 33.625,28.708 34,28.333 34,25.625 34.375,25.25 37.375,25.25 39.5,23.125 v1(40.375,23.125) ; U1.AA5@55.5,22.5 v1(56,23.125)
  Layer 8 w0.104: v1(40.375,23.125) 44.25,23.125 47.75,19.625 53,19.625 53.5,20.125 53.5,22 54.625,23.125 v1(56,23.125)
RGMII_TX_CTL: U1.W4 U10.25 | length 21.3
  Top Layer w0.2: U10.25@35.375,29.95 35.375,29.6 35.85,29.125 36.5,29.125 36.875,28.75 38.125,28.75 38.75,28.125 v1(38.75,27.5) ; v1(53,25.75) U1.W4@53.5,26.5
  Layer 3 w0.104: v1(38.75,27.5) 40.5,27.5 41,28 50.125,28 52.375,25.75 v1(53,25.75)
RGMII_TXC: U1.U4 U10.24 | length 20.7
  Top Layer w0.2: U10.24@34.625,29.3 34.625,29 34.875,28.75 36.375,28.75 37.25,27.875 v1(38,27.875) ; v1(52.625,30.375) U1.U4@53.5,30.5
  Layer 3 w0.104: v1(38,27.875) 38.25,28.125 40.375,28.125 40.625,28.375 49.25,28.375 51.25,30.375 v1(52.625,30.375)
RS232_1_CTS_N: J29.4 U8.6 | length 24.5
  Top Layer w0.125: v1(23.25,53.25) U8.6@23.25,55.203
  Layer 10 w0.125: J29.4@2.125,51.125 4.125,53.125 6.875,53.125 7.5,52.5 16.125,52.5 16.875,53.25 v1(23.25,53.25)
RS232_1_RTS_N: J29.3 U8.11 | length 29.2
  Top Layer w0.125: v1(26.5,51.75) U8.11@26.5,55.203
  Layer 10 w0.125: J29.3@2.125,49.875 3.5,49.875 4.25,49.125 6.646,49.125 7.396,49.875 17.875,49.875 19.75,51.75 v1(26.5,51.75)
RS232_1_RX: J29.2 U8.5 | length 26.4
  Top Layer w0.125: v1(22.625,49.875) U8.5@22.625,55.228
  Layer 10 w0.125: J29.2@2.125,48.625 6.5,48.625 7.5,49.625 18.75,49.625 19,49.875 v1(22.625,49.875)
RS232_1_TX: J29.1 U8.10 | length 30.6
  Top Layer w0.125: v1(25.875,49.375) U8.10@25.875,55.228
  Layer 10 w0.125: J29.1@2.125,47.375 5.625,47.375 7.625,49.375 19,49.375 19.25,49.625 21.875,49.625 22.125,49.375 v1(25.875,49.375)
RS232_3_CTS_N: J29.9 U9.5 | length 38.2
  Top Layer w0.125: U9.5@37.125,55 v1(37.125,56.5)
  Layer 10 w0.125: J29.9@2.125,57.375 3,57.375 5,55.375 7,55.375 7.75,56.125 17,56.125 17.5,55.625 36.25,55.625 v1(37.125,56.5)
RS232_3_RTS_N: J29.8 U9.10 | length 40.7
  Top Layer w0.125: U9.10@40.375,55 v1(40.375,56.5)
  Layer 10 w0.125: J29.8@2.125,56.125 3.25,56.125 4.25,55.125 39,55.125 v1(40.375,56.5)
RS232_3_RX: J29.7 U9.4 | length 36.2
  Top Layer w0.125: v1(36.5,53.625) U9.4@36.5,54.975
  Layer 10 w0.125: J29.7@2.125,54.875 18,54.875 18.125,54.75 35.375,54.75 v1(36.5,53.625)
RS232_3_TX: J29.6 U9.9 | length 40
  Top Layer w0.125: v1(39.75,53.625) U9.9@39.75,54.975
  Layer 10 w0.125: J29.6@2.125,53.625 18.75,53.625 19.5,54.375 33.625,54.375 34.875,53.125 39.25,53.125 v1(39.75,53.625)
SATA_RX_N: C16.1 U1.G19 | length 17.2
  Top Layer w0.122: U1.G19@83.5,50.5 v1(84.125,49.875)
  Layer 8 w0.101: v1(84.125,49.875) 84.35,49.65 84.726,49.65 85.375,50.299 85.375,60.625 86.35,61.6 86.35,63.525 v1(86.125,63.75)
  Bottom Layer w0.122: C16.1@85.875,64.415 86.125,64.165 v1(86.125,63.75)
SATA_RX_P: C17.1 U1.H19 | length 17.7
  Top Layer w0.122: U1.H19@83.5,48.5 v1(84.125,49.125)
  Layer 8 w0.101: v1(84.125,49.125) 84.35,49.35 84.85,49.35 85.675,50.175 85.675,60.501 86.65,61.476 86.65,63.525 v1(86.875,63.75)
  Bottom Layer w0.122: v1(86.875,63.75) 86.875,64.165 C17.1@87.125,64.415
SATA_TX_N: C15.1 U1.D19 | length 11.2
  Top Layer w0.122: v1(82.875,55.875) U1.D19@83.5,56.5
  Layer 8 w0.101: v1(82.875,55.875) 82.65,55.65 82.399,55.65 81.625,56.424 81.625,60.326 82.65,61.351 82.65,63.525 v1(82.875,63.75)
  Bottom Layer w0.122: v1(82.875,63.75) 82.875,64.165 C15.1@83.125,64.415
SATA_TX_P: C14.1 U1.E19 | length 11.7
  Top Layer w0.122: v1(82.875,55.125) U1.E19@83.5,54.5
  Layer 8 w0.101: v1(82.125,63.75) 82.35,63.525 82.35,61.475 81.325,60.45 81.325,56.3 82.275,55.35 82.65,55.35 v1(82.875,55.125)
  Bottom Layer w0.122: C14.1@81.875,64.415 82.125,64.165 v1(82.125,63.75)
SATARX_N: C16.2 J8.5 | length 4.8
  Bottom Layer w0.122: C16.2@85.875,65.335 86.375,65.835 86.375,67.288 86.837,67.75 86.837,68.993 J8.5@86.33,69.5
SATARX_P: C17.2 J8.6 | length 4.8
  Bottom Layer w0.122: C17.2@87.125,65.335 86.63,65.83 86.63,67.182 87.093,67.644 87.093,68.993 J8.6@87.6,69.5
SATATX_N: C15.2 J8.3 | length 4.9
  Bottom Layer w0.122: C15.2@83.125,65.335 82.63,65.83 82.63,67.117 83.283,67.769 83.283,68.993 J8.3@83.79,69.5
SATATX_P: C14.2 J8.2 | length 4.9
  Bottom Layer w0.122: C14.2@81.875,65.335 82.375,65.835 82.375,67.223 83.027,67.875 83.027,68.993 J8.2@82.52,69.5
SD2_CLK: R35.1 U1.K22 | length 1.5
  Top Layer w0.2: U1.K22@89.5,44.5 v1(89.5,45.375)
  Bottom Layer w0.2: v1(89.5,45.375) R35.1@89.5,46.02
SD2_CMD: J7.3 R30.1 U1.M20 | length 55.6
  Top Layer w0.2: v1(84.25,44.5) 84.25,42.5 85.5,41.25 U1.M20@85.5,40.5 v1(84.5,39.875)
  Layer 3 w0.104: v1(74.75,6.375) 74.75,8 74.875,8.125 75.125,8.125 75.375,8.375 75.375,9.5 75.125,9.75 74.875,9.75 74.75,9.875 74.75,10.125 74.875,10.25 77.5,10.25 77.625,10.375 77.625,10.625 77.5,10.75 74.25,10.75 74.125,10.875 74.125,11.125 74.25,11.25 78,11.25 79,12.25 79,13.125 82,16.125 82,18.25 84.038,20.288 84.038,24.337 83,25.375 83,27.75 84.25,29 84.25,30 84.875,30.625 84.875,39.5 v1(84.5,39.875)
  Bottom Layer w0.2: J7.3@74.75,5.3 v1(74.75,6.375) ; v1(84.25,44.5) R30.1@85.02,44.5
SD2_DAT0: J7.7 R34.1 U1.P24 | length 58.6
  Top Layer w0.2: U1.P24@93.5,36.5 v1(94.125,37.125)
  Layer 3 w0.104: v1(79.125,6.5) 79.5,6.125 81.25,6.125 82.875,7.75 82.875,10.875 90,18 90,19.75 93.625,23.375 93.625,30.375 93.5,30.5 93.375,30.5 93.25,30.375 93.25,24 93.125,23.875 92.875,23.875 92.75,24 92.75,30.625 93,30.875 93,31.625 93.25,31.875 93.25,36.25 v1(94.125,37.125)
  Bottom Layer w0.2: J7.7@79.125,5.275 v1(79.125,6.5) ; R34.1@93.98,40.5 94.375,40.105 94.375,37.375 v1(94.125,37.125)
SD2_DAT1: J7.8 R33.1 U1.K21 | length 55.5
  Top Layer w0.125: U1.K21@87.5,44.5 v1(87.5,45.375)
  Layer 3 w0.104: v1(77.25,8.25) 78.625,8.25 78.75,8.375 78.75,8.75 78.625,8.875 78.25,8.875 78.125,9 78.125,9.375 78.25,9.5 80.375,9.5 80.5,9.625 80.5,10 80.375,10.125 78.25,10.125 78.125,10.25 78.125,10.625 78.25,10.75 80,10.75 80.25,11 80.25,13.75 82.375,15.875 82.375,17.375 85.25,20.25 85.25,24.625 85.913,25.288 85.913,30.587 85.5,31 85.5,43.375 v1(87.5,45.375)
  Bottom Layer w0.125: R33.1@87.5,46.02 R33.1@87.5,46.145
  Bottom Layer w0.2: v1(77.25,8.25) 78.75,8.25 80.2,6.8 J7.8@80.2,5.25 ; v1(87.5,45.375) R33.1@87.5,46.02
SD2_DAT2: J7.1 R32.1 U1.R24 | length 62.8
  Top Layer w0.2: U1.R24@93.5,34.5 v1(94.125,35.125)
  Layer 3 w0.104: v1(72.5,6.375) 72.5,5.125 73.375,4.25 76.5,4.25 76.625,4.375 76.625,4.625 76.5,4.75 73.625,4.75 73.5,4.875 73.5,5.125 73.625,5.25 80.875,5.25 83.25,7.625 83.25,10.875 94.663,22.288 94.663,30.454 94.125,30.992 v1(94.125,35.125)
  Bottom Layer w0.2: J7.1@72.5,5.25 v1(72.5,6.375) ; R32.1@93.98,42.5 94.875,41.605 94.875,35.875 v1(94.125,35.125)
SD2_DAT3: J7.2 R31.1 U1.K23 | length 55.6
  Top Layer w0.125: U1.K23@91.5,44.5 v1(91.5,45.375)
  Layer 3 w0.104: v1(73.6,6.875) 74.763,5.712 77.837,5.712 78.5,6.375 78.5,6.75 78.75,7 79.375,7 79.875,6.5 81.125,6.5 82.375,7.75 82.375,13.25 85.625,16.5 85.625,17.25 87.75,19.375 87.75,21.625 89,22.875 89,26.375 88.125,27.25 88.125,32.875 89.5,34.25 89.5,43.375 v1(91.5,45.375)
  Bottom Layer w0.2: J7.2@73.6,5.65 v1(73.6,6.875) ; v1(91.5,45.375) R31.1@91.5,46.02
SHLD: C33.1 J7.11 J7.12 J13.SHLD1 J13.SHLD2 J15.SH1 J15.SH2 J15.SH3 J15.SH4 J16.6 J16.7 J16.8 J16.9 P1.M1 P1.M2 P1.M3 P1.M4 R46.2 | length 25.9
  Top Layer w0.25: J15.SH3@40.57,7.67 P1.M2@44.325,7.65
  Top Layer w1: J13.SHLD2@24.462,11.048 J15.SH2@27.43,13.35 ; J15.SH3@40.57,7.67 J15.SH4@40.57,13.35
  Bottom Layer w0.25: v1(15.375,1.5) R46.2@16.105,1.5 ; C33.1@17.25,1.5 v1(18,1.5)
  Bottom Layer w0.5: J16.9@30.55,1.5 J16.8@33.15,1.5 J16.7@35.45,1.5 J16.6@38.05,1.5
  Bottom Layer w1: J13.SHLD2@24.462,11.048 J15.SH2@27.43,13.35
  other v1: 8.5,1.25 9.75,1.25 11,1.25 12.25,1.25 13.5,1.25 14.75,1.25 18.75,1.25 20,1.25 21.25,1.25 22.5,1.25 23.75,1.25 25,1.25 26.25,1.25 27.5,1.25 28.75,1.25 39.75,1.25 41,1.25 42.25,1.25 43.75,1.25 45,1.25 46.375,1.25 49.25,1.25 50.5,1.25 51.75,1.25 53,1.25 54.25,1.25 55.5,1.25 58.5,1.25 62.5,1.25 63.75,1.25 65,1.25 66.25,1.25 69.375,1.25 70.625,1.25 71.875,1.25 73.125,1.25 74.375,1.25 75.75,1.25 77,1.25 78.25,1.25 79.75,1.5 82.25,1.5 79.75,2.25 82.25,2.25 38.375,3 39.75,3 28.75,3.125 30.125,3.125 38.375,4.25 30.125,4.375 38.375,5.5 30.125,5.625
SPI1_CLK: J34.1 U1.AD20 | length 31.7
  Top Layer w0.125: U1.AD20@85.5,16.5 v1(86.25,17.25)
  Layer 3 w0.125: v1(86.25,17.25) 86.625,16.875 87.625,16.875 89.25,18.5 89.25,20.25 91.663,22.663 91.663,29.087 91.5,29.25 91.5,31.917 92.75,33.167 92.75,36.5 J34.1@97.875,41.625
SPI1_MISO: J34.2 U1.V17 | length 34.9
  Top Layer w0.125: U1.V17@79.5,28.5 v1(80.125,29.125)
  Layer 10 w0.125: v1(80.125,29.125) 80.5,28.75 83.75,28.75 84.125,29.125 84.125,30.625 83.875,30.875 83.875,31.5 85.5,33.125 85.5,38.75 92.875,46.125 93.75,46.125 95.75,44.125 95.75,41.625 97,40.375 J34.2@97.875,40.375
SPI1_MOSI: J34.3 U1.AB18 | length 29.8
  Top Layer w0.125: U1.AB18@81.5,20.5 v1(82.125,21.125)
  Layer 10 w0.125: v1(82.125,21.125) 84.75,23.75 92.25,23.75 95.375,26.875 95.375,36.625 J34.3@97.875,39.125
SPI1_SS0: J34.4 U1.Y24 | length 15.2
  Top Layer w0.125: U1.Y24@93.5,24.5 95.125,26.125 95.125,35.125 J34.4@97.875,37.875
SPI1_SS1/SPI1_IRQ_N: J34.5 R122.2 U1.K2 | length 135.8
  Top Layer w0.125: U1.K2@49.5,44.5 v1(50,43.75)
  Layer 8 w0.125: v1(32,59.875) 32.5,60.375 33.25,60.375 35.125,58.5 44.875,58.5 49.5,53.875 49.5,44.25 v1(50,43.75)
  Bottom Layer w0.125: v1(32,59.875) 30.625,61.25 30.625,68.625 31.25,69.25 55.75,69.25 56.75,70.25 65.75,70.25 70.75,65.25 78.729,65.25 80.854,63.125 89.625,63.125 90.25,62.5 90.25,55.625 91.625,54.25 91.625,48.73 96,44.355 96,38.5 J34.5@97.875,36.625 ; R122.2@47.98,44.5 48.73,43.75 v1(50,43.75)
TOUCH_X1: J30.1 U1.T23 | length 126.7
  Top Layer w0.125: U1.T23@91.5,32.5 v1(92.25,33.25)
  Layer 8 w0.125: J30.1@2.125,8.375 4.75,11 4.75,16 5.5,16.75 7.875,16.75 11.375,13.25 23.375,13.25 24,13.875 24,15 25.25,16.25 25.875,16.25 26.75,17.125 31.875,17.125 33.25,15.75 38.125,15.75 39.5,17.125 42.125,17.125 47.75,11.5 59.5,11.5 61.625,13.625 65.375,13.625 66.25,12.75 74,12.75 76.375,15.125 89.375,15.125 95.538,21.288 95.538,30.837 93.125,33.25 v1(92.25,33.25)
TOUCH_X2: J30.2 U1.R23 | length 121.6
  Top Layer w0.125: v1(91.5,33.5) U1.R23@91.5,34.5
  Layer 8 w0.125: J30.2@2.125,9.625 4.5,12 4.5,16.125 5.375,17 8.25,17 9.875,15.375 22.75,15.375 24.75,17.375 32.125,17.375 32.625,16.875 34.875,16.875 35.5,16.25 38.25,16.25 39.375,17.375 42.625,17.375 48.125,11.875 59.5,11.875 61.5,13.875 73.875,13.875 75.5,15.5 88.5,15.5 94.663,21.663 94.663,31.087 93.125,32.625 92,32.625 91.5,33.125 v1(91.5,33.5)
TOUCH_Y1: J30.3 U1.U24 | length 115.1
  Top Layer w0.125: U1.U24@93.5,30.5 v1(93.5,31.375)
  Layer 8 w0.125: J30.3@2.125,10.875 4,12.75 4,16.125 5.125,17.25 8.375,17.25 10,15.625 22.625,15.625 24.625,17.625 32.875,17.625 33.375,17.125 35,17.125 35,17.104 35.604,16.5 38.125,16.5 39.25,17.625 42.75,17.625 47.538,12.837 59.837,12.837 61.125,14.125 72.25,14.125 74,15.875 88.521,15.875 93.5,20.854 v1(93.5,31.375)
TOUCH_Y2: J30.4 U1.R22 | length 117
  Top Layer w0.125: v1(89.5,33.5) U1.R22@89.5,34.5
  Layer 8 w0.125: J30.4@2.125,12.125 3.625,13.625 3.625,16.25 4.875,17.5 8.5,17.5 10.125,15.875 22.5,15.875 24.5,17.875 33.375,17.875 33.875,17.375 35.125,17.375 35.75,16.75 38,16.75 39.125,17.875 43,17.875 47.663,13.212 58.191,13.212 59.354,14.375 72,14.375 73.875,16.25 88.5,16.25 92.625,20.375 92.625,30.375 v1(89.5,33.5)
UART1_CTS_N: U1.Y17 U8.12 | length 161.5
  Top Layer w0.125: v1(5,45.875) 4,44.875 4,27.125 v1(5.75,25.375) ; v1(27.25,53.875) U8.12@27.25,55.197 ; v1(78.625,24.5) U1.Y17@79.5,24.5
  Layer 3 w0.125: v1(5,45.875) 5,47.125 7.5,49.625 18,49.625 22.25,53.875 v1(27.25,53.875) ; v1(5.75,25.375) 5.75,19.25 12.5,12.5 17.375,12.5 19.625,10.25 19.625,7 21.5,5.125 28.75,5.125 32.375,8.75 37.75,8.75 39.375,10.375 47.875,10.375 48.625,9.625 56.75,9.625 57.25,10.125 59.5,10.125 61.75,12.375 65.875,12.375 67.5,10.75 67.5,6.75 68.625,5.625 69.875,5.625 71.875,7.625 71.875,9 73.625,10.75 73.625,11.125 74.25,11.75 76.625,11.75 79.5,14.625 79.5,23.625 v1(78.625,24.5)
UART1_RTS_N: U1.W19 U8.17 | length 104
  Top Layer w0.125: v1(27.25,60.875) U8.17@27.25,62.197 ; U1.W19@83.5,26.5 v1(83.5,27.5)
  Layer 3 w0.125: v1(27.25,60.875) 27.25,64.5 29.125,66.375 29.125,68.375 31.25,70.5 65.875,70.5 77.625,58.75 83.25,58.75 85.5,56.5 85.5,49.25 86.125,48.625 86.125,47 85.125,46 85.125,30.5 84.5,29.875 84.5,28.5 v1(83.5,27.5)
UART1_RX: U1.E21 U8.18 | length 84.4
  Top Layer w0.125: v1(26.625,60.25) U8.18@26.625,62.172 ; v1(86.625,55.125) U1.E21@87.5,54.5
  Layer 8 w0.125: v1(26.625,60.25) 26.625,67.875 27.75,69 53,69 55.375,66.625 64.875,66.625 65.875,65.625 86.75,65.625 88.25,64.125 88.25,56.75 v1(86.625,55.125)
UART1_TX: U1.C21 U8.13 | length 82.1
  Top Layer w0.125: U8.13@27.875,55.278 v1(27.875,56.625) ; v1(86.5,57.625) U1.C21@87.5,58.5
  Layer 8 w0.125: v1(27.875,56.625) 29.125,57.875 29.125,67.25 30.625,68.75 52.875,68.75 55.25,66.375 64.75,66.375 65.75,65.375 86.5,65.375 87.875,64 87.875,59 v1(86.5,57.625)
UART3_CTS_N: U1.Y15 U9.13 | length 75.6
  Top Layer w0.125: v1(42.375,53.625) U9.13@42.375,54.95 ; v1(74.75,25.25) U1.Y15@75.5,24.5
  Layer 5 w0.125: v1(42.375,53.625) 45.75,53.625 46.75,52.625 47.875,52.625 50.25,50.25 51,50.25 51.375,49.875 53.375,49.875 55.125,48.125 55.125,27.687 60,22.812 60,20 59.375,19.375 59.375,15.75 60.375,14.75 63.521,14.75 64.375,15.604 64.375,16.5 66.875,19 69.25,19 71.625,21.375 71.625,23.375 71.375,23.625 71.375,25 72.125,25.75 74.25,25.75 v1(74.75,25.25)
